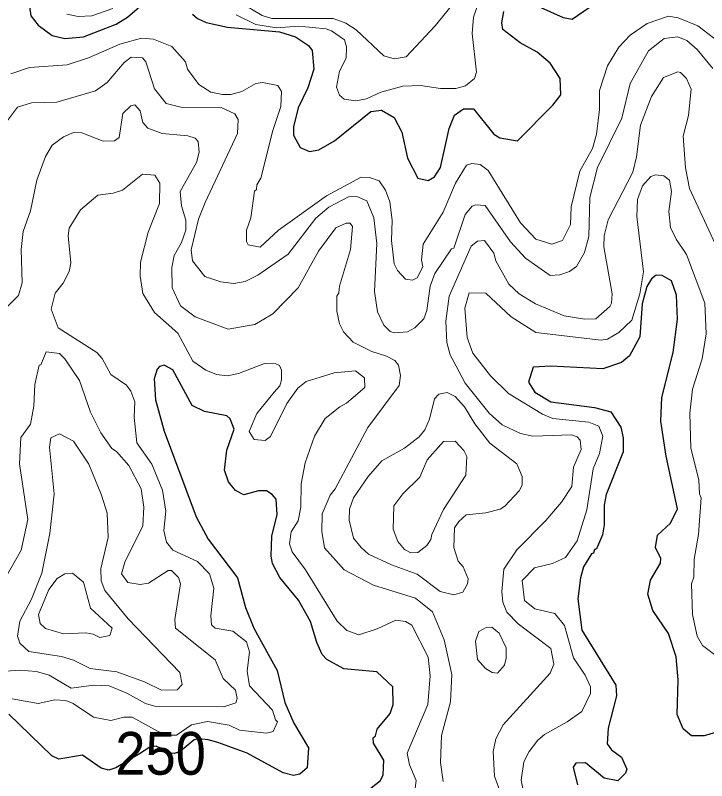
# Model space of a CAD drawing. Extents: x 763.2 to 816.8, y 7896.5 to 7952.7.
# Drawn here: x 780.054 to 782.642, y 7901.054 to 7903.918 of the extents above; entities that cross this region are included whole.
import ezdxf
from ezdxf.enums import TextEntityAlignment as Align

# ---------------------------------------------------------------- set-up
doc = ezdxf.new("R2010")
doc.units = 0
doc.header["$LTSCALE"] = 0.064
doc.layers.add('1', color=7, linetype='Continuous', lineweight=25)
doc.layers.add('2', color=7, linetype='Continuous', lineweight=13)
doc.layers.add('61', color=7, linetype='Continuous')

msp = doc.modelspace()

# ---------------------------------------------------------------- linework, layer by layer
at = {"layer": '1'}
for points in [[(780.1073, 7903.9501), (780.1122, 7903.9159), (780.1397, 7903.8813), (780.1919, 7903.8426), (780.2396, 7903.8314), (780.3094, 7903.8375), (780.4309, 7903.8848), (780.4733, 7903.9115), (780.5544, 7903.9825)], [(781.3852, 7903.5578), (781.4253, 7903.5631), (781.4724, 7903.5356), (781.5009, 7903.4812), (781.5223, 7903.3834), (781.5607, 7903.309), (781.5994, 7903.3007), (781.6228, 7903.3138), (781.6455, 7903.3489), (781.6785, 7903.4944), (781.698, 7903.5446), (781.7324, 7903.568), (781.7688, 7903.568), (781.8454, 7903.474), (781.8673, 7903.4594), (781.9337, 7903.4484), (782.0668, 7903.5821), (782.0958, 7903.6202), (782.0943, 7903.6813), (782.0564, 7903.7391), (782.0077, 7903.7799), (781.9437, 7903.8149), (781.8795, 7903.8655), (781.8758, 7903.8896), (781.8823, 7903.9324)], [(782.0098, 7903.9519), (782.1054, 7903.9102), (782.1386, 7903.9039), (782.2021, 7903.9478)], [(780.7173, 7903.9231), (780.7358, 7903.9066), (780.7683, 7903.8917), (780.8484, 7903.8743), (781.0433, 7903.8568), (781.1034, 7903.8382), (781.1516, 7903.8057), (781.1651, 7903.7871), (781.1721, 7903.7163), (781.1495, 7903.6464), (781.1125, 7903.5716), (781.0951, 7903.5009), (781.0953, 7903.47), (781.1205, 7903.4235), (781.1558, 7903.4086), (781.1902, 7903.4147), (781.2493, 7903.4484), (781.3852, 7903.5578)], [(782.5104, 7902.9245), (782.4762, 7902.9449), (782.4533, 7902.9453), (782.4361, 7902.9322), (782.4178, 7902.9033), (782.4002, 7902.8382), (782.3915, 7902.7146), (782.3529, 7902.6444), (782.3231, 7902.6189), (782.2529, 7902.5955), (782.0582, 7902.6053), (781.9922, 7902.6012), (781.9746, 7902.5453), (781.9993, 7902.5086), (782.0584, 7902.4718), (782.2223, 7902.4511), (782.2831, 7902.4341), (782.3205, 7902.3775), (782.3292, 7902.3367), (782.3292, 7902.2845), (782.2656, 7902.125), (782.2581, 7902.0856), (782.2585, 7902.0121), (782.2523, 7901.9743), (782.2293, 7901.9213), (782.2227, 7901.9194), (782.2191, 7901.906), (782.2115, 7901.9034), (782.1815, 7901.8542), (782.1696, 7901.813), (782.1601, 7901.7352), (782.175, 7901.6178), (782.3024, 7901.4112), (782.3044, 7901.3712), (782.2735, 7901.2502), (782.2701, 7901.1918), (782.2855, 7901.1701), (782.3229, 7901.1418), (782.3437, 7901.0977), (782.3383, 7901.082), (782.3094, 7901.0542), (782.2586, 7901.0639), (782.1888, 7901.1212), (782.1525, 7901.1194), (782.1423, 7901.1044), (782.1582, 7901.0391)], [(782.4707, 7902.3991), (782.4744, 7902.4886), (782.5165, 7902.6562), (782.5328, 7902.7811), (782.5294, 7902.8706), (782.5104, 7902.9245)], [(781.351, 7901.0006), (781.4214, 7901.0553), (781.4315, 7901.0758), (781.4336, 7901.1313), (781.3951, 7901.1951), (781.3942, 7901.2151), (781.402, 7901.2217), (781.4087, 7901.2471), (781.4567, 7901.3061), (781.468, 7901.339), (781.4677, 7901.4053), (781.4071, 7901.4611), (781.2842, 7901.4732), (781.22, 7901.5077), (781.2024, 7901.5268), (781.1825, 7901.5708), (781.1593, 7901.6497), (781.1142, 7901.7299), (781.0441, 7901.8149), (781.0163, 7901.8674), (781.0112, 7901.8945), (781.0143, 7901.9693), (781.0338, 7902.0497), (781.0306, 7902.1072), (781.0153, 7902.1257), (780.9939, 7902.1384), (780.9644, 7902.1384), (780.9097, 7902.1237), (780.8776, 7902.14), (780.8524, 7902.1724), (780.8371, 7902.2159), (780.8453, 7902.2914), (780.8727, 7902.3695), (780.8582, 7902.4079), (780.8459, 7902.4195), (780.7622, 7902.4358), (780.7164, 7902.4584), (780.6434, 7902.5914), (780.6106, 7902.6094), (780.5942, 7902.6045), (780.585, 7902.5937), (780.5742, 7902.5576), (780.5791, 7902.4788), (780.6113, 7902.3621), (780.7306, 7902.041), (780.7763, 7901.9578), (780.8858, 7901.8137), (780.9161, 7901.7023), (780.9468, 7901.6248), (781.034, 7901.4664), (781.0625, 7901.3473), (781.0967, 7901.2692), (781.1519, 7901.1767), (781.1467, 7901.1024), (781.1189, 7901.0785), (781.0959, 7901.0739), (781.0566, 7901.0837), (780.9217, 7901.1575), (780.8123, 7901.1968), (780.7765, 7901.2072), (780.7413, 7901.2106), (780.7229, 7901.2072), (780.6715, 7901.1628)], [(782.6758, 7901.2341), (782.6324, 7901.2218), (782.5851, 7901.2222), (782.5542, 7901.2485), (782.5317, 7901.3014), (782.5361, 7901.4321), (782.5282, 7901.5182), (782.4996, 7901.6051), (782.4407, 7901.6907), (782.4214, 7901.7517), (782.4314, 7901.8049), (782.4689, 7901.8681), (782.4701, 7901.8861), (782.451, 7901.9273), (782.4584, 7901.9734), (782.5062, 7902.018), (782.5328, 7902.0719), (782.4908, 7902.2683), (782.4707, 7902.3991)], [(780.5189, 7901.1551), (780.4302, 7901.1021), (780.4041, 7901.094), (780.3756, 7901.101), (780.305, 7901.1503), (780.217, 7901.1347), (780.191, 7901.1468), (780.0299, 7901.3034)], [(780.6715, 7901.1628), (780.649, 7901.1565), (780.6369, 7901.1576), (780.5813, 7901.1831), (780.5573, 7901.179), (780.5189, 7901.1551)]]:
    msp.add_lwpolyline(points, dxfattribs=at)
at = {"layer": '2'}
for points in [[(781.6851, 7903.9529), (781.6258, 7903.879), (781.5169, 7903.7624), (781.4726, 7903.7557), (781.434, 7903.7662), (781.3306, 7903.8637), (781.2913, 7903.8885), (781.2435, 7903.9062), (781.0139, 7903.9069), (780.9777, 7903.9182), (780.9049, 7903.9613)], [(781.7728, 7903.6816), (781.7803, 7903.7054), (781.7644, 7903.8505), (781.7689, 7903.9118), (781.7906, 7903.9726)], [(780.2462, 7903.9222), (780.2888, 7903.9135), (780.3401, 7903.9166), (780.4189, 7903.9443)], [(782.7263, 7903.789), (782.6091, 7903.8785), (782.5356, 7903.9087), (782.499, 7903.9149), (782.419, 7903.8875), (782.3559, 7903.8444), (782.314, 7903.7994), (782.2707, 7903.7291), (782.2408, 7903.6364), (782.2405, 7903.5661), (782.2302, 7903.4732), (782.2145, 7903.4199), (782.1677, 7903.3352), (782.1352, 7903.2012), (782.1319, 7903.1351), (782.1026, 7903.0757), (782.0623, 7903.0622), (782.0028, 7903.0803), (781.9451, 7903.1422), (781.8242, 7903.3371), (781.7942, 7903.3597), (781.7635, 7903.3642), (781.7426, 7903.3574), (781.7015, 7903.2906), (781.6553, 7903.1822), (781.5813, 7903.0615), (781.5751, 7903.0037), (781.5796, 7902.9768), (781.5586, 7902.9363), (781.5413, 7902.9277), (781.5146, 7902.931), (781.485, 7902.9631), (781.4726, 7902.9889), (781.462, 7903.0758), (781.4647, 7903.1518), (781.4565, 7903.2207), (781.4403, 7903.2637), (781.4157, 7903.2983), (781.38, 7903.3117), (781.3492, 7903.3121), (781.219, 7903.2432), (781.0392, 7903.1147), (780.9701, 7903.0501), (780.9261, 7903.0593), (780.9192, 7903.072), (780.9192, 7903.1149), (780.9355, 7903.1608), (780.9491, 7903.2608), (780.9567, 7903.2664), (780.9587, 7903.2834), (780.9733, 7903.3087), (781.0177, 7903.4872), (781.0475, 7903.5772), (781.0503, 7903.6337), (781.0363, 7903.6557), (780.9795, 7903.667), (780.9544, 7903.6636), (780.9013, 7903.6335), (780.8605, 7903.6217), (780.8299, 7903.6214), (780.7863, 7903.6313), (780.7407, 7903.6597), (780.6989, 7903.7171), (780.6906, 7903.744), (780.6402, 7903.8012), (780.5707, 7903.8295), (780.5263, 7903.8328), (780.4452, 7903.8097), (780.3275, 7903.759), (780.2478, 7903.7333), (780.1073, 7903.7228), (780.0377, 7903.6994)], [(780.8813, 7903.9202), (780.9539, 7903.8844), (781.0314, 7903.8716), (781.1157, 7903.8773), (781.2179, 7903.8674), (781.2373, 7903.8606), (781.2862, 7903.827), (781.2937, 7903.8), (781.2922, 7903.7585), (781.2678, 7903.7087), (781.2561, 7903.6495), (781.2675, 7903.6195), (781.2855, 7903.6044), (781.3289, 7903.5979), (781.3681, 7903.6059), (781.4226, 7903.6305), (781.5049, 7903.6537), (781.5714, 7903.6553), (781.6463, 7903.644), (781.7028, 7903.6442), (781.7387, 7903.6539), (781.7728, 7903.6816)], [(782.6648, 7903.7196), (782.6069, 7903.7902), (782.5677, 7903.8236), (782.5348, 7903.8378), (782.4832, 7903.8314), (782.4239, 7903.7858), (782.3557, 7903.6629), (782.3243, 7903.5339), (782.2334, 7903.3483), (782.2045, 7903.2359), (782.2009, 7903.0902), (782.1844, 7903.0303)], [(781.9645, 7903.0096), (781.9081, 7903.071), (781.8134, 7903.2062), (781.7784, 7903.2097), (781.7642, 7903.2038), (781.7386, 7903.1735), (781.6952, 7903.0468), (781.6873, 7903.044), (781.6243, 7902.952), (781.6074, 7902.9045), (781.5945, 7902.8141), (781.5829, 7902.7828), (781.5491, 7902.7488), (781.5219, 7902.7343), (781.4735, 7902.7303), (781.4576, 7902.7348), (781.4336, 7902.7583), (781.4096, 7902.8083), (781.399, 7902.8853), (781.4072, 7903.0645), (781.3957, 7903.1604), (781.3693, 7903.2246), (781.3319, 7903.2397), (781.3011, 7903.2394), (781.2276, 7903.1998), (781.1789, 7903.1591), (781.0757, 7903.0249), (780.9619, 7902.9455), (780.9145, 7902.922), (780.8724, 7902.9144), (780.8238, 7902.9209), (780.7628, 7902.9409), (780.7168, 7902.9991), (780.7123, 7903.0401), (780.7399, 7903.1551), (780.7647, 7903.2183), (780.8863, 7903.4754), (780.8878, 7903.5281), (780.8754, 7903.5493), (780.8244, 7903.573), (780.6733, 7903.575), (780.6185, 7903.5883), (780.5753, 7903.6428), (780.5424, 7903.7445), (780.53, 7903.759), (780.4882, 7903.7622), (780.4614, 7903.7415), (780.3976, 7903.6664), (780.3538, 7903.6359), (780.2097, 7903.5937), (780.114, 7903.5913), (780.0619, 7903.5749), (780.0174, 7903.5148)], [(782.7298, 7902.942), (782.5784, 7903.2699), (782.5627, 7903.3472), (782.5545, 7903.4655), (782.5739, 7903.5431), (782.5839, 7903.6416), (782.5672, 7903.682), (782.5439, 7903.7046), (782.5347, 7903.7062), (782.4812, 7903.6852), (782.4361, 7903.6143), (782.3951, 7903.5075), (782.3799, 7903.3886), (782.3659, 7903.3314), (782.2735, 7903.1525), (782.2586, 7903.0934), (782.257, 7903.0525), (782.2881, 7902.8757)], [(780.6712, 7903.2586), (780.7323, 7903.3676), (780.7416, 7903.4063), (780.7381, 7903.4456), (780.7274, 7903.458), (780.6996, 7903.4678), (780.6031, 7903.4754), (780.55, 7903.4961), (780.5315, 7903.5166), (780.5209, 7903.5609), (780.501, 7903.5828), (780.4863, 7903.5798), (780.4563, 7903.5505), (780.4424, 7903.4605), (780.4257, 7903.448), (780.3824, 7903.4479), (780.3035, 7903.4788), (780.2712, 7903.4795), (780.2342, 7903.464), (780.1918, 7903.4323), (780.1669, 7903.3897), (780.1349, 7903.3009), (780.111, 7903.1868), (780.0832, 7903.1088), (780.076, 7903.0424), (780.0793, 7902.9166), (780.0661, 7902.8701), (780.0251, 7902.8288)], [(780.0423, 7901.3611), (780.1395, 7901.3432), (780.2017, 7901.3564), (780.2425, 7901.3545), (780.271, 7901.3434), (780.3462, 7901.292), (780.4113, 7901.2793), (780.4597, 7901.2922), (780.4918, 7901.292), (780.5889, 7901.238), (780.6285, 7901.2242), (780.657, 7901.2245), (780.7141, 7901.2635), (780.7738, 7901.2757), (780.854, 7901.2622), (780.8936, 7901.2429), (780.9939, 7901.2315), (781.0198, 7901.2384), (781.0359, 7901.2739), (781.0278, 7901.2813), (781.0164, 7901.3178), (780.9301, 7901.4092), (780.9224, 7901.4641), (780.9305, 7901.5361), (780.9196, 7901.5739), (780.8678, 7901.6136), (780.8021, 7901.6245), (780.788, 7901.6376), (780.7862, 7901.6708), (780.7975, 7901.7746), (780.7808, 7901.8278), (780.7361, 7901.8743), (780.6439, 7901.9163), (780.6203, 7901.9469), (780.6104, 7901.9908), (780.6168, 7902.0622), (780.605, 7902.1409), (780.5644, 7902.2382), (780.5085, 7902.3181), (780.4986, 7902.414), (780.5017, 7902.4714), (780.4865, 7902.5122), (780.4702, 7902.5345), (780.4111, 7902.5746), (780.3792, 7902.6344), (780.3596, 7902.6569), (780.2139, 7902.7491), (780.1882, 7902.8192), (780.2025, 7902.8791), (780.2325, 7902.9165), (780.2549, 7902.9599), (780.2615, 7902.9917), (780.2521, 7903.093), (780.2552, 7903.1223), (780.298, 7903.1903), (780.3625, 7903.2454), (780.4205, 7903.2523), (780.4551, 7903.2641), (780.5304, 7903.3234), (780.5767, 7903.32), (780.5954, 7903.2899), (780.5939, 7903.2141), (780.5517, 7903.107), (780.5231, 7902.9942), (780.5215, 7902.9416), (780.5313, 7902.8772), (780.575, 7902.8064), (780.6627, 7902.7285), (780.7188, 7902.6235), (780.7671, 7902.5909), (780.8075, 7902.5741), (780.8475, 7902.5693), (780.8897, 7902.5784), (780.9873, 7902.615), (781.0295, 7902.6135), (781.0427, 7902.6077), (781.0506, 7902.5903), (781.0505, 7902.5536), (781.044, 7902.5323), (781.0233, 7902.5086), (780.9587, 7902.4277), (780.9294, 7902.3606), (780.9487, 7902.3315), (780.9891, 7902.3277), (781.0089, 7902.3419), (781.0708, 7902.4655), (781.112, 7902.5233), (781.1429, 7902.5475), (781.2478, 7902.5806), (781.3277, 7902.5882), (781.3611, 7902.5618), (781.362, 7902.5257), (781.2942, 7902.4663), (781.2688, 7902.4533), (781.2145, 7902.409)], [(781.9645, 7900.9767), (781.9481, 7901.0556), (781.9581, 7901.1244), (781.9773, 7901.1633), (782.01, 7901.2062), (782.0348, 7901.2274), (782.1202, 7901.2748), (782.1744, 7901.3137), (782.2075, 7901.381), (782.2071, 7901.4053), (782.1878, 7901.4496), (782.1434, 7901.5137), (782.1102, 7901.6343), (782.0733, 7901.6797), (781.9991, 7901.6971), (781.9605, 7901.7282), (781.9513, 7901.8036), (781.9974, 7901.8508), (782.0649, 7901.8669), (782.1142, 7901.8897), (782.1579, 7901.9522), (782.1942, 7902.0673), (782.2176, 7902.2216), (782.2416, 7902.2786), (782.2536, 7902.3432), (782.2386, 7902.3808), (782.2009, 7902.3955), (782.0657, 7902.41), (782.0275, 7902.4259), (781.9008, 7902.5029), (781.8333, 7902.5692), (781.7669, 7902.6536), (781.7458, 7902.7128), (781.7362, 7902.822), (781.7527, 7902.8794), (781.8158, 7902.878), (781.9101, 7902.79), (782.0027, 7902.7318), (782.2471, 7902.7023), (782.2711, 7902.7061), (782.3128, 7902.7319), (782.3618, 7902.7779), (782.3924, 7902.8763), (782.4062, 7902.9582), (782.3802, 7903.1657), (782.3832, 7903.2291), (782.4019, 7903.2806), (782.4329, 7903.3151), (782.4507, 7903.3215), (782.482, 7903.3171), (782.5031, 7903.3018), (782.5101, 7903.2594), (782.5002, 7903.1847), (782.5064, 7903.1241), (782.5276, 7903.0805), (782.5661, 7903.0237), (782.6358, 7902.8411), (782.6399, 7902.7267), (782.6248, 7902.6326), (782.5892, 7902.5189)], [(780.649, 7903.0194), (780.6762, 7903.0678), (780.6923, 7903.1139), (780.6922, 7903.1518), (780.676, 7903.2052), (780.6712, 7903.2586)], [(781.6557, 7901.0516), (781.6456, 7901.122), (781.6489, 7901.2234), (781.683, 7901.3498), (781.6884, 7901.4514), (781.6589, 7901.5808), (781.6152, 7901.686), (781.5521, 7901.7366), (781.3943, 7901.7858), (781.2852, 7901.8434), (781.2119, 7901.9255), (781.2019, 7901.9865), (781.2032, 7902.0522), (781.2329, 7902.123), (781.251, 7902.1468), (781.3741, 7902.3762), (781.4906, 7902.5326), (781.4959, 7902.5707), (781.4879, 7902.6094), (781.4744, 7902.6264), (781.444, 7902.6426), (781.3891, 7902.6597), (781.3191, 7902.695), (781.2821, 7902.7339), (781.2679, 7902.7641), (781.2578, 7902.8115), (781.2578, 7902.8669), (781.2657, 7902.8792), (781.2682, 7902.9051), (781.3088, 7903.0415), (781.3164, 7903.1274), (781.3071, 7903.1404), (781.292, 7903.141), (781.2538, 7903.1235), (781.1891, 7903.0355), (781.1125, 7902.8989), (781.0182, 7902.8011), (780.9506, 7902.7618), (780.8508, 7902.7434), (780.7276, 7902.7897), (780.672, 7902.8313), (780.6415, 7902.8988), (780.6398, 7902.975), (780.649, 7903.0194)], [(782.109, 7902.7943), (782.0017, 7902.8381), (781.9398, 7902.8765), (781.902, 7902.9126), (781.8534, 7903), (781.8458, 7903.0276), (781.8101, 7903.0753), (781.7838, 7903.0734), (781.7605, 7903.0548), (781.6786, 7902.8673), (781.6653, 7902.7738), (781.6689, 7902.6934), (781.6813, 7902.6474), (781.7378, 7902.5413), (781.8281, 7902.4295), (781.8763, 7902.3864), (781.9454, 7902.3537), (781.9914, 7902.344), (782.1358, 7902.3489), (782.1577, 7902.3404), (782.1682, 7902.3284), (782.1729, 7902.293), (782.144, 7902.2271), (782.1369, 7902.1556), (782.0986, 7902.0969), (782.0405, 7902.0273), (781.9316, 7901.9183), (781.8825, 7901.8457), (781.8757, 7901.7622), (781.8792, 7901.7221), (781.8944, 7901.6853), (781.9365, 7901.6407), (782.0592, 7901.5488), (782.0695, 7901.4908), (782.056, 7901.4567), (781.8807, 7901.2632), (781.853, 7901.2107), (781.8428, 7901.1633), (781.848, 7901.0713), (781.8949, 7900.9419)], [(782.1844, 7903.0303), (782.1546, 7902.9785), (782.1293, 7902.9598), (782.092, 7902.947), (782.0566, 7902.9451), (781.9645, 7903.0096)], [(782.2881, 7902.8757), (782.2865, 7902.8416), (782.2792, 7902.8285), (782.2268, 7902.783), (782.1865, 7902.7812), (782.109, 7902.7943)], [(780.0003, 7901.7846), (780.0762, 7901.9174), (780.1007, 7902.0319), (780.0696, 7902.2395), (780.0745, 7902.3379), (780.1104, 7902.3882), (780.1236, 7902.4551), (780.1274, 7902.5369), (780.1433, 7902.609), (780.1496, 7902.6108), (780.1691, 7902.6593), (780.2192, 7902.6523), (780.2389, 7902.6327), (780.2942, 7902.5516), (780.3358, 7902.4327), (780.3739, 7902.356), (780.4157, 7902.2971), (780.4326, 7902.2864), (780.4792, 7902.2336), (780.5248, 7902.1462), (780.5346, 7902.0777), (780.5311, 7902.0082), (780.4643, 7901.8713), (780.4511, 7901.8277), (780.4757, 7901.7955), (780.5214, 7901.7885), (780.552, 7901.7934), (780.626, 7901.8406), (780.6384, 7901.8407), (780.6642, 7901.8147), (780.6726, 7901.7905), (780.6514, 7901.657), (780.6534, 7901.6244), (780.8015, 7901.5068), (780.8321, 7901.4369), (780.8783, 7901.3932), (780.8844, 7901.362), (780.8795, 7901.3451), (780.8343, 7901.33), (780.5799, 7901.3318), (780.5413, 7901.3433), (780.4711, 7901.3822), (780.4058, 7901.4089), (780.3479, 7901.4121), (780.2629, 7901.4007), (780.1802, 7901.4496), (780.1329, 7901.4632), (780.0702, 7901.4681), (780.0003, 7901.4631)], [(782.5892, 7902.5189), (782.5791, 7902.4294), (782.5824, 7902.2987), (782.6125, 7902.1804), (782.6154, 7902.1272), (782.6217, 7902.1131)], [(781.2145, 7902.409), (781.1737, 7902.3434), (781.1389, 7902.243), (781.1245, 7902.1651), (781.1229, 7902.0778), (781.1131, 7902.0261)], [(782.6217, 7902.1131), (782.6119, 7901.9758), (782.5955, 7901.8831), (782.5939, 7901.8163), (782.5857, 7901.7911), (782.5891, 7901.6757), (782.6064, 7901.5944), (782.6264, 7901.5605), (782.671, 7901.5268)], [(781.1131, 7902.0261), (781.0869, 7901.9857), (781.0805, 7901.9399), (781.0904, 7901.9103), (781.1397, 7901.8437), (781.2593, 7901.6506), (781.2951, 7901.6165), (781.3394, 7901.5997), (781.4089, 7901.6226), (781.479, 7901.655), (781.5141, 7901.6502), (781.5384, 7901.6358), (781.5993, 7901.5164), (781.6076, 7901.446), (781.5983, 7901.3397), (781.5208, 7901.1574), (781.5298, 7901.1138), (781.555, 7901.0544), (781.5473, 7900.9974)]]:
    msp.add_lwpolyline(points, dxfattribs=at)
for points in [[(781.6229, 7902.4825), (781.639, 7902.5), (781.6704, 7902.5066), (781.7006, 7902.4916), (781.7353, 7902.4527), (781.7742, 7902.3895), (781.8303, 7902.3171), (781.9316, 7902.2396), (781.9512, 7902.1927), (781.9512, 7902.1595), (781.9397, 7902.1386), (781.8871, 7902.0811), (781.8692, 7902.0699), (781.8153, 7902.0563), (781.7422, 7902.0493), (781.714, 7902.0246), (781.6986, 7902.0006), (781.6955, 7901.9274), (781.7115, 7901.8755), (781.7305, 7901.8546), (781.7489, 7901.8091), (781.7468, 7901.7904), (781.7297, 7901.7595), (781.6954, 7901.7495), (781.645, 7901.7626), (781.5586, 7901.8269), (781.4624, 7901.8618), (781.3765, 7901.9021), (781.3482, 7901.9266), (781.3206, 7901.9623), (781.3038, 7902.0292), (781.3054, 7902.0703), (781.3204, 7902.1121), (781.3754, 7902.1924), (781.4256, 7902.2517), (781.5114, 7902.2984), (781.5654, 7902.3413), (781.5869, 7902.3668), (781.6043, 7902.4065)], [(780.1828, 7901.9798), (780.1994, 7902.1282), (780.1814, 7902.302), (780.1865, 7902.3368), (780.2194, 7902.3519), (780.2722, 7902.3249), (780.3294, 7902.2382), (780.377, 7902.123), (780.3981, 7902.0547), (780.4015, 7901.9642), (780.3736, 7901.8476), (780.3752, 7901.8023), (780.3885, 7901.7656), (780.476, 7901.6598), (780.6693, 7901.4589), (780.6789, 7901.4146), (780.6593, 7901.3942), (780.6011, 7901.3926), (780.5379, 7901.4236), (780.4341, 7901.461), (780.3341, 7901.4746), (780.2723, 7901.5055), (780.2271, 7901.5185), (780.1045, 7901.5374), (780.0707, 7901.5688), (780.0615, 7901.5952), (780.0705, 7901.6514), (780.114, 7901.7333), (780.1533, 7901.8312)], [(781.7409, 7902.1975), (781.7441, 7902.2671), (781.7329, 7902.2898), (781.7012, 7902.3242), (781.6573, 7902.324), (781.596, 7902.2546), (781.5681, 7902.1896), (781.5053, 7902.1282), (781.4716, 7902.0824), (781.4681, 7901.9956), (781.4862, 7901.9496), (781.5107, 7901.919), (781.5348, 7901.907), (781.5612, 7901.9086), (781.5941, 7901.9344), (781.6092, 7901.9565), (781.6129, 7901.9757), (781.6575, 7902.0685)], [(780.1799, 7901.7691), (780.211, 7901.8112), (780.2388, 7901.8278), (780.2681, 7901.831), (780.3091, 7901.7965), (780.3356, 7901.7002), (780.417, 7901.6253), (780.4081, 7901.5971), (780.3709, 7901.5897), (780.3454, 7901.6026), (780.3177, 7901.6076), (780.2337, 7901.6043), (780.1665, 7901.6242), (780.1474, 7901.6426), (780.1402, 7901.6757)], [(781.8648, 7901.6067), (781.8376, 7901.6284), (781.8172, 7901.6274), (781.7891, 7901.6129), (781.7772, 7901.5769), (781.7842, 7901.5071), (781.8145, 7901.4735), (781.8394, 7901.4587), (781.8591, 7901.4569), (781.8848, 7901.4864), (781.8918, 7901.5127), (781.8918, 7901.5518)]]:
    msp.add_lwpolyline(points, close=True, dxfattribs=at)

# ---------------------------------------------------------------- texts
at = {"layer": '61', "width": 0.95}
msp.add_text('250', height=0.16, dxfattribs=at).set_placement((780.5978, 7901.0765), align=Align.CENTER)

doc.saveas('drawing.dxf')
